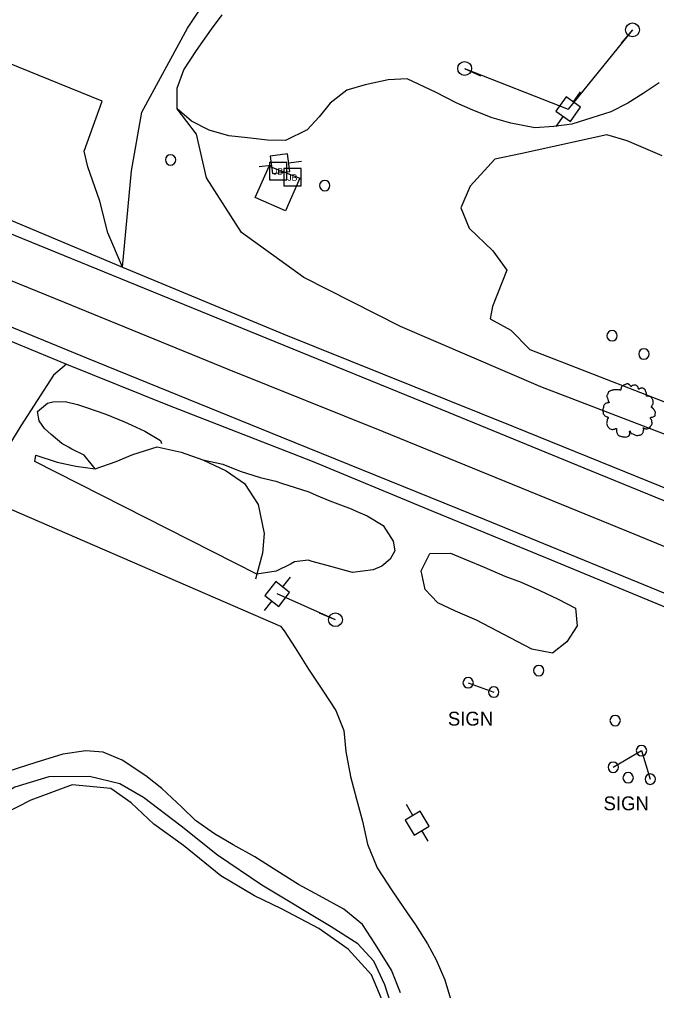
# Model space of a CAD drawing. Extents: x 2160437 to 2172832, y 205694 to 212444.
# Drawn here: x 2160853.5 to 2161037.4, y 211247.9 to 211528.1 of the extents above; entities that cross this region are included whole.
import ezdxf

# ---------------------------------------------------------------- set-up
doc = ezdxf.new("R2010")
doc.units = 0
for name, color, linetype in [('Default', 7, 'Continuous'), ('RD_EX_Bldg_Signs', 7, 'Continuous'), ('RD_EX_BldgApp_txCode', 7, 'Continuous'), ('RD_EX_ConcPad', 7, 'Continuous'), ('RD_EX_DR_Inlet', 7, 'Continuous'), ('RD_EX_Driveway', 7, 'Continuous'), ('RD_EX_H2O', 7, 'Continuous'), ('RD_EX_LaneStripe', 7, 'Continuous'), ('RD_EX_Road', 7, 'Continuous'), ('RD_EX_Road_Post', 7, 'Continuous'), ('RD_EX_UT', 7, 'Continuous'), ('RD_EX_UT_Guy', 7, 'Continuous'), ('RD_EX_VEG', 7, 'Continuous'), ('RD_EX_VEG_ShrubLine', 7, 'Continuous'), ('RD_EX_VEG_TreeLine', 7, 'Continuous')]:
    doc.layers.add(name, color=color, linetype=linetype)

# ---------------------------------------------------------------- blocks, each defined once
blk = doc.blocks.new('POST')
at = {"layer": 'Default'}
for start, end in [(90, 270), (270, 90)]:
    blk.add_arc((0, 0), 0.0417, start, end, dxfattribs=at)
blk = doc.blocks.new('T2')
at = {"layer": 'RD_EX_VEG'}
for points in [[(0.05, 7.21), (-0.25, 7.24), (-0.57, 7.14), (-0.82, 7.04), (-1.05, 6.96), (-1.27, 6.86), (-1.57, 6.69), (-1.8, 6.49), (-1.92, 6.24), (-1.97, 6.01), (-2.02, 5.74), (-2.02, 5.56), (-2.15, 5.54), (-2.3, 5.56), (-2.55, 5.64), (-2.8, 5.64), (-3.05, 5.64), (-3.4, 5.61), (-3.75, 5.61), (-4.02, 5.56), (-4.35, 5.51), (-4.72, 5.39), (-5.07, 5.26), (-5.37, 5.01), (-5.62, 4.54), (-5.75, 4.19), (-5.9, 3.94), (-5.75, 3.49), (-5.57, 3.14), (-5.55, 2.94), (-5.47, 2.52), (-5.37, 2.29), (-5.25, 2.09), (-5.32, 2.07), (-5.7, 2.02), (-6, 1.92), (-6.42, 1.69), (-6.64, 1.47), (-6.74, 1.14), (-6.77, 0.79), (-6.87, 0.59), (-6.94, 0.32), (-6.97, 0.24), (-7.02, -0.08), (-6.92, -0.53), (-6.89, -0.88), (-6.77, -1.11), (-6.62, -1.28), (-6.44, -1.53), (-6.05, -1.76), (-5.72, -1.86), (-5.52, -1.88), (-5.7, -2.38), (-5.75, -2.73), (-5.87, -3.13), (-5.87, -3.21), (-5.92, -3.68), (-5.77, -4.01), (-5.7, -4.38), (-5.52, -4.61), (-5.25, -4.91), (-4.92, -5.13), (-4.42, -5.26), (-4.02, -5.23), (-3.45, -5.06), (-3.2, -4.98), (-3.22, -5.16), (-3.2, -5.53), (-3.2, -5.96), (-3.05, -6.28), (-2.95, -6.56), (-2.8, -6.81), (-2.47, -7.03), (-2.07, -7.11), (-1.65, -7.26), (-1.2, -7.33), (-0.7, -7.36), (-0.1, -7.21), (0.18, -7.08), (0.28, -6.91), (0.48, -6.53), (0.43, -6.31), (0.45, -5.71), (0.55, -5.88), (0.73, -6.23), (1.23, -6.53), (1.63, -6.71), (2.1, -6.86), (2.4, -6.93), (2.88, -6.86), (3.25, -6.78), (3.63, -6.66), (3.93, -6.38), (4.1, -6.11), (4.15, -5.83), (4.23, -5.46), (4.28, -5.28)], [(4.28, -5.28), (4.2, -5.11), (4.15, -4.86), (4.23, -4.88), (4.4, -4.93), (4.68, -5.06), (4.9, -5.13), (5.23, -5.11), (5.5, -5.01), (5.95, -4.73), (6.22, -4.26), (6.5, -3.86), (6.57, -3.53), (6.52, -3.31), (6.5, -2.81), (6.3, -2.56), (6.25, -2.43), (6.15, -2.03), (6.22, -1.98), (6.5, -1.93), (6.87, -1.81), (7.15, -1.68), (7.37, -1.51), (7.45, -1.28), (7.42, -0.88), (7.47, -0.48), (7.4, -0.33), (7.3, -0.18), (7.22, 0.02), (7.07, 0.17), (6.97, 0.32), (6.87, 0.42), (6.75, 0.57), (6.57, 0.69), (6.42, 0.74), (6.37, 0.89), (6.52, 1.09), (6.57, 1.19), (6.6, 1.42), (6.82, 1.77), (6.87, 2.17), (6.82, 2.59), (6.77, 2.87), (6.62, 3.14), (6.42, 3.39), (6.3, 3.56), (6.12, 3.69), (5.8, 3.81), (5.55, 3.86), (5.2, 3.86), (5, 3.91), (5.03, 3.96), (5.03, 4.11), (5.03, 4.39), (4.95, 4.84), (4.8, 5.34), (4.8, 5.36), (4.7, 5.61), (4.48, 5.81), (4.3, 5.91), (4.1, 6.04), (3.85, 6.06), (3.55, 6.06), (3.28, 6.01), (3.08, 5.91), (2.9, 5.79), (2.83, 5.94), (2.73, 6.24), (2.68, 6.39), (2.53, 6.56), (2.3, 6.76), (1.85, 6.89), (1.23, 6.81), (0.93, 6.61), (0.78, 6.44), (0.73, 6.56), (0.53, 6.76), (0.43, 6.94), (0.25, 7.06), (0.1, 7.16), (0, 7.21)]]:
    blk.add_spline(points, degree=3, dxfattribs=at)
blk = doc.blocks.new('PP')
at = {"layer": 'RD_EX_UT'}
for p, q in [((2.49, 2.51), (-2.51, 2.51)), ((-2.51, 2.51), (-2.51, -2.49)), ((2.49, -2.49), (2.49, 2.51)), ((-5.94, -0.05), (-2.47, -0.05)), ((-2.51, -2.49), (2.49, -2.49)), ((2.42, -0.05), (6.06, -0.05))]:
    blk.add_line(p, q, dxfattribs=at)

msp = doc.modelspace()

# ---------------------------------------------------------------- linework, layer by layer
at = {"layer": 'RD_EX_Bldg_Signs'}
for points in [[(2160983, 211336.73), (2160990.38, 211334.05)], [(2161024.88, 211312.35), (2161033.02, 211317.15), (2161035.56, 211308.93)]]:
    msp.add_lwpolyline(points, dxfattribs=at)
at = {"layer": 'RD_EX_ConcPad'}
msp.add_lwpolyline([(2160921.51, 211476.76), (2160925.55, 211485.81), (2160934.44, 211482.31), (2160930.3, 211472.89)], close=True, dxfattribs=at)
at = {"layer": 'RD_EX_DR_Inlet'}
for p, q in [((2160930.66, 211481.83), (2160930.66, 211486.83)), ((2160934.78, 211480.06), (2160934.78, 211485.06))]:
    msp.add_line(p, q, dxfattribs=at)
for points in [[(2160930.66, 211481.83), (2160930.66, 211486.83), (2160925.66, 211486.83), (2160925.66, 211481.83)], [(2160934.78, 211480.06), (2160934.78, 211485.06), (2160929.78, 211485.06), (2160929.78, 211480.06)]]:
    msp.add_lwpolyline(points, close=True, dxfattribs=at)
at = {"layer": 'RD_EX_Driveway'}
for points in [[(2160883.23, 211456.65), (2160885.84, 211484.42), (2160888.83, 211501.37), (2160902.04, 211525.55), (2160915.43, 211545.66), (2160938.89, 211554.9), (2160982.05, 211588.89), (2161007.21, 211609.28), (2161044.05, 211635.27), (2161067.57, 211655.89), (2161084.34, 211672.85), (2161095.05, 211692.02), (2161112.22, 211725.71), (2161126.03, 211747.77), (2161142.28, 211766.52)], [(2160883.23, 211456.65), (2160879, 211466.5), (2160876.76, 211475.62), (2160873.24, 211485.61), (2160872.19, 211490.08), (2160877.38, 211504.47), (2160801.37, 211535.47), (2160793.74, 211517.33), (2160789.21, 211509.88), (2160782.08, 211504.37), (2160776.76, 211501.45)], [(2160867.15, 211428.64), (2160863.33, 211425.45), (2160853.96, 211410.88), (2160840.58, 211389.14), (2160792.63, 211315.35), (2160773.57, 211295.38), (2160759.86, 211281.49), (2160746.12, 211261.36), (2160735.08, 211241.98), (2160725.38, 211218), (2160721.23, 211201.93), (2160716.18, 211188.34), (2160716.46, 211182.31), (2160719.86, 211175.5), (2160721.93, 211173.17), (2160732.85, 211161.18)]]:
    msp.add_lwpolyline(points, dxfattribs=at)
at = {"layer": 'RD_EX_H2O'}
msp.add_lwpolyline([(2160959.42, 211242.23), (2160955.11, 211252.52), (2160948.38, 211259.91), (2160939.96, 211265.87), (2160929.19, 211271.5), (2160921.32, 211275.23), (2160911.63, 211281.07), (2160900.88, 211289.82), (2160892.36, 211295.94), (2160885.82, 211302.08), (2160879.92, 211306.2), (2160868.71, 211307.28), (2160856.82, 211302.88), (2160837.78, 211293.2), (2160834, 211292.13), (2160820.01, 211284.39), (2160815.62, 211280.82), (2160807.54, 211273.48), (2160797.01, 211263.02), (2160794, 211259.81), (2160786.86, 211252.1), (2160780.67, 211244.7)], dxfattribs=at)
at = {"layer": 'RD_EX_LaneStripe'}
msp.add_lwpolyline([(2161313.27, 211264.6), (2161243.32, 211292.98), (2161172.39, 211321.94), (2161101.86, 211350.38), (2161088.83, 211355.74), (2161030.92, 211379.58), (2160958.6, 211409.12), (2160914.08, 211427.02), (2160866.52, 211446.42), (2160807.69, 211470.39), (2160755.29, 211491.95)], dxfattribs=at)
at = {"layer": 'RD_EX_Road'}
for points in [[(2160759.52, 211507.49), (2160776.76, 211501.45), (2160797.69, 211492.55), (2160883.23, 211456.65), (2160929.81, 211437.3), (2160996.12, 211410.66), (2161066.77, 211382.02), (2161117.09, 211360.94), (2161178.47, 211336.33), (2161226.02, 211317.11), (2161284.16, 211293.28), (2161319.97, 211278.3)], [(2161318.72, 211275.71), (2161259.77, 211299.48), (2161207.02, 211321.22), (2161142.16, 211347.35), (2161062.6, 211379.76), (2161018.64, 211397.79), (2160975.19, 211415.58), (2160924.71, 211436.19), (2160852.42, 211465.68), (2160785.13, 211493.08), (2160758.35, 211504.2)], [(2160750.75, 211480.71), (2160799.35, 211460.67), (2160872.87, 211430.45), (2160928.96, 211407.72), (2160987.67, 211383.93), (2161049.11, 211358.69), (2161055.24, 211356.18), (2161084.03, 211344.24), (2161115.64, 211331.4), (2161116.89, 211330.9), (2161182.93, 211304.43), (2161230.86, 211284.89), (2161308.93, 211252.7)], [(2160749.45, 211477.45), (2160787.08, 211461.89), (2160832.84, 211442.88), (2160844.69, 211437.92), (2160867.15, 211428.64), (2160896.23, 211416.95), (2160937.96, 211400.63), (2160971.37, 211386.8), (2161006.95, 211372.17), (2161055.51, 211352.11)]]:
    msp.add_lwpolyline(points, dxfattribs=at)
at = {"layer": 'RD_EX_UT'}
for p, q in [((2161030.41, 211525.07), (2161027.2, 211521.24)), ((2160981.99, 211513.92), (2160986.52, 211511.81)), ((2160944.71, 211354.92), (2160940.1, 211356.85))]:
    msp.add_line(p, q, dxfattribs=at)
for centre in [(2161030.41, 211525.07), (2160981.99, 211513.92), (2160944.71, 211354.92)]:
    msp.add_circle(centre, 2, dxfattribs=at)
at = {"layer": 'RD_EX_UT_Guy'}
for points in [[(2161030.41, 211525.07), (2161011.89, 211502.19)], [(2160981.99, 211513.92), (2161011.89, 211502.19)], [(2160944.71, 211354.92), (2160927.93, 211362.36)]]:
    msp.add_lwpolyline(points, dxfattribs=at)
at = {"layer": 'RD_EX_VEG_ShrubLine'}
for points in [[(2161080.51, 211392.8), (2161004.01, 211422.12), (2160963.48, 211439.54), (2160935.6, 211453.68), (2160917.58, 211466.59), (2160907.48, 211482.4), (2160904.63, 211495.04), (2160899.02, 211502.33)], [(2161038.95, 211488.77), (2161028.86, 211493.11), (2161023.04, 211494.82), (2160998.08, 211489.33), (2160990.67, 211487.81), (2160983.56, 211480.03), (2160980.92, 211473.7), (2160983.27, 211467.89), (2160990.13, 211461.3), (2160994.12, 211455.79), (2160990.04, 211445.24), (2160989.38, 211441.72), (2160995.31, 211438.45), (2161000.77, 211432.85), (2161051.3, 211413.22)], [(2160875.35, 211398.45), (2160872.18, 211402.44), (2160868.69, 211404.08), (2160867.7, 211404.7), (2160865.81, 211405.78), (2160862.74, 211408.33), (2160860.74, 211410.05), (2160859.21, 211412.31), (2160858.8, 211414.98), (2160861.64, 211417.41), (2160863.13, 211417.77), (2160866.7, 211417.84), (2160870.27, 211417.03), (2160872.64, 211416.25), (2160878.43, 211414.2), (2160878.43, 211414.2), (2160883.87, 211412.03), (2160885.99, 211411.07), (2160889.76, 211409.3), (2160894.28, 211406.62), (2160894.55, 211405.75)], [(2160906.42, 211401.06), (2160912.18, 211399.84), (2160917.22, 211397.8), (2160922.98, 211395.94), (2160927.55, 211394.91), (2160929.16, 211394.36), (2160937.04, 211391.83), (2160939.16, 211390.87), (2160943.12, 211389.25), (2160949.23, 211386.89), (2160950.67, 211386.24), (2160953.87, 211384.85), (2160958.46, 211382.07), (2160958.46, 211382.07), (2160961.37, 211377.63), (2160961.88, 211374.79), (2160960.48, 211372.35), (2160958.08, 211370.37), (2160955.62, 211369.28), (2160949.61, 211368.53), (2160949.61, 211368.53), (2160943.35, 211370.32), (2160938.03, 211371.75), (2160936.84, 211372.06), (2160932.86, 211371.6), (2160931.75, 211370.94), (2160927.58, 211368.89), (2160922.04, 211368.04), (2160921.69, 211366.59)], [(2160961.41, 211242.05), (2160958.97, 211249.58), (2160955.75, 211256.43), (2160951.22, 211261.38), (2160943.5, 211266.32), (2160923.44, 211278.3), (2160910.64, 211286.99), (2160900.23, 211295.35), (2160889.38, 211303.63), (2160882.5, 211307.61), (2160873.76, 211309.66), (2160861.98, 211309.61), (2160852.22, 211306.61), (2160842.67, 211300.86), (2160833.19, 211296.06), (2160821.11, 211289.19), (2160812.15, 211281.32), (2160799.66, 211268.56), (2160784.35, 211253.31), (2160768.59, 211230.91)]]:
    msp.add_lwpolyline(points, dxfattribs=at)
msp.add_lwpolyline([(2160985.4, 211354.82), (2160979.4, 211357.43), (2160974.23, 211359.83), (2160970.57, 211363.63), (2160969.44, 211369.06), (2160971.94, 211374.07), (2160977.88, 211374.16), (2160982.52, 211372.24), (2160987.58, 211370.11), (2160993.56, 211367.46), (2160998.33, 211365.71), (2161003.71, 211363.39), (2161008.95, 211360.9), (2161013.94, 211358.24), (2161014.47, 211353.13), (2161011.46, 211348.53), (2161007.31, 211345.25), (2161001.41, 211346.42)], close=True, dxfattribs=at)
at = {"layer": 'RD_EX_VEG_TreeLine'}
for points in [[(2161038.15, 211509.85), (2161033.5, 211506.75), (2161029.12, 211503.98), (2161024.17, 211501.48), (2161018.71, 211499.66), (2161012.93, 211497.88), (2161007.76, 211497.21), (2161002.25, 211496.81), (2160995.35, 211498.2), (2160989.91, 211499.74), (2160984.4, 211501.88), (2160979.59, 211504.06), (2160973.77, 211507.05), (2160965.45, 211510.93), (2160959.89, 211510.67), (2160953.33, 211509.24), (2160948.01, 211507.71), (2160943.15, 211503.89), (2160940, 211499.99), (2160936.55, 211496.22), (2160930.3, 211493.15), (2160925.14, 211493.28), (2160919.31, 211493.95), (2160914, 211494.5), (2160908.27, 211496.17), (2160903.17, 211498.71), (2160899.02, 211502.33), (2160899.03, 211508.23), (2160900.99, 211513.6), (2160904.65, 211519.12), (2160908.95, 211525.28), (2160912, 211529.46)], [(2160848.33, 211387.98), (2160928.87, 211353.04), (2160929.94, 211351.73), (2160933.06, 211346.84), (2160936.98, 211340.66), (2160941.19, 211334.35), (2160944.8, 211328.78), (2160947.15, 211322.97), (2160947.76, 211316.9), (2160949.03, 211309.72), (2160950.79, 211303.13), (2160952.55, 211296.78), (2160953.94, 211290.13), (2160956.79, 211283.39), (2160961.06, 211276.71), (2160964.32, 211271.87), (2160967.77, 211266.95), (2160971.29, 211261.42), (2160973.73, 211256.84), (2160976.31, 211251.04), (2160977.89, 211245.57)], [(2160963.52, 211247.33), (2160960.9, 211253.85), (2160956.27, 211261.27), (2160956.27, 211261.27), (2160952.51, 211267.03), (2160947.1, 211271.45), (2160940.15, 211275.29), (2160934.08, 211278.5), (2160927.79, 211282.51), (2160921.49, 211286.52), (2160915.17, 211289.96), (2160909.81, 211293.2), (2160904.33, 211296.96), (2160900.4, 211300.82), (2160894.62, 211306.22), (2160890.04, 211309.91), (2160883.16, 211314.42), (2160877.74, 211316.76), (2160872.67, 211317.08), (2160866.1, 211316.12), (2160858.3, 211313.74), (2160850.19, 211311.17)]]:
    msp.add_lwpolyline(points, dxfattribs=at)
msp.add_lwpolyline([(2160922.04, 211368.04), (2160857.96, 211400.55), (2160858.25, 211402.38), (2160864.42, 211400.39), (2160869.8, 211399.23), (2160875.35, 211398.45), (2160881.41, 211400.57), (2160886.24, 211402.55), (2160893.29, 211404.81), (2160900.24, 211403.28), (2160906.42, 211401.06), (2160913.2, 211397.88), (2160918.49, 211394.21), (2160918.49, 211394.21), (2160922.45, 211388.13), (2160924.14, 211379.83), (2160923.65, 211374.15)], close=True, dxfattribs=at)

# ---------------------------------------------------------------- block references
at = {"layer": 'RD_EX_Road_Post', "xscale": 36, "yscale": 36}
for p in [(2160897.16, 211487.55), (2160941.63, 211480.15), (2161024.54, 211436.84), (2161033.72, 211431.58), (2161003.38, 211340.24), (2160983, 211336.73), (2160990.38, 211334.05), (2161025.43, 211325.83), (2161033.02, 211317.15), (2161024.88, 211312.35), (2161029.17, 211309.34), (2161035.56, 211308.93)]:
    msp.add_blockref('POST', p, dxfattribs=at)
at = {"layer": 'RD_EX_UT'}
for p, xscale, yscale, rotation in [((2161011.89, 211502.19), 1.0199999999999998, 1.02, -125.39597600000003), ((2160928.74, 211486.45), 1.02, 1.0199999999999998, 7.357946), ((2160927.93, 211362.36), 1.0199999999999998, 1.02, 52.056383), ((2160968.29, 211296.25), 1.02, 1.0199999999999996, 120.69827200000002)]:
    msp.add_blockref('PP', p, dxfattribs=dict(at, xscale=xscale, yscale=yscale, rotation=rotation))
at = {"layer": 'RD_EX_VEG', "xscale": 1.0499999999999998, "yscale": 1.0499999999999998}
msp.add_blockref('T2', (2161029.18, 211415.36), dxfattribs=at)

# ---------------------------------------------------------------- texts
at = {"layer": 'RD_EX_BldgApp_txCode'}
for p in [(2160977.16, 211324.38), (2161022.07, 211299.96)]:
    msp.add_text('SIGN', height=4, dxfattribs=at).set_placement(p)
at = {"layer": 'RD_EX_DR_Inlet'}
for p in [(2160926.69, 211483.31), (2160930.81, 211481.54)]:
    msp.add_text('JB', height=1.875, dxfattribs=at).set_placement(p)

doc.saveas('drawing.dxf')
